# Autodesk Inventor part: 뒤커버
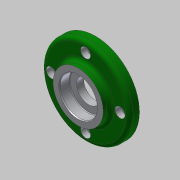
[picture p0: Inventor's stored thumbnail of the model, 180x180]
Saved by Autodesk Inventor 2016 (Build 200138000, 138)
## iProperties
Created: 2019-01
Part Number: 뒤커버
Material: 알루미늄 6061
Document SubType Name: Modeling
Designer: mduedu
Density: 1 g/cm^3
Appearance: 알루미늄 - 평지
Author: mduedu
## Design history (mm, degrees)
sketch "스케치1"
  geometry: L1 (0, 0)-(6, 0); L2 (6, 0)-(6, 20); L3 (6, 20)-(0, 20); L4 (0, 20)-(0, 0); L5 (6, 0)-(14, 0); L6 (14, 0)-(14, 35); L7 (14, 35)-(6, 35); L8 (6, 35)-(6, 0); L9 (14, 0)-(19, 0); L10 (19, 0)-(19, 20); L11 (19, 20)-(14, 20); L12 (14, 20)-(14, 0)
  constraints: 24 end point, 6 parallel, 3 horizontal, 3 perpendicular
  dimensions: "d6" = 70 diameter of L7 L5; "d8" = 40 diameter of L3 L1; "d9" = 40 diameter of L11 L9; "d10" = 5 distance of L10.end L11.end; "d11" = 6 distance of L2.end L3.end; "d12" = 19 distance between parallel lines of L4 L10; "d13" = 8 distance of L6.end L7.end (derived)
revolve "회전1" sketch "스케치1" stored, may be unused: angle "d5" = 90 deg
sketch "스케치2" dims "d14" = 55
  geometry: 7 further points
  constraints: 2 coincident, 2 vertical alignment, 7 other
  dimensions: "d17" = 360 deg dimension on point (0, 0) point (0, 27.5) (derived)
sketch "스케치3"
  geometry: 4 further points
  constraints: 4 other
hole "구멍1" sketch "스케치3" at (0, 27.5), (-27.5, 0), (27.5, 0), (0, -27.5) diameter "d19" = 4.5; stored, may be unused: countersink angle "d23" = 90 deg, drill point angle "d25" = 0 deg; dims "d20" = 6, "d21" = 8, "d22" = 4.6, "d24" = 8
fillet "모깎기1" dims "d26" = 3
sketch "스케치4"
  geometry: C1 r 9.5 at (0, 0); 1 further point
  constraints: 1 centre point, 1 coincident
  dimensions: "d27" = 19 diameter of C1
extrude "돌출1" cut sketch "스케치4" stored distance "d28" = 10; taper "d29" = 0 deg
sketch "스케치5"
  geometry: C1 r 15 at (0, 0); 1 further point
  constraints: 1 centre point, 1 coincident
  dimensions: "d31" = 30 diameter of C1
extrude "돌출2" cut sketch "스케치5" distance "d32" = 8.3; taper "d33" = 0 deg
chamfer "모따기1" distance "d34" = 0.8; stored, may be unused: second distance "d35" = 2, angle "d36" = 30 deg
fillet "모깎기2" dims "d37" = 3
fillet "모깎기3" dims "d38" = 0.5
sketch "스케치6"
  geometry: C1 r 16.5 at (0, 0); 1 further point
  constraints: 1 centre point, 1 coincident
  dimensions: "d39" = 33 diameter of C1
extrude "돌출3" cut sketch "스케치6" distance "d40" = 5; taper "d41" = 0 deg
fillet "모깎기4" dims "d42" = 3
chamfer "모따기2" distance "d43" = 1; stored, may be unused: second distance "d44" = 2, angle "d45" = 30 deg
node "솔리드1"
